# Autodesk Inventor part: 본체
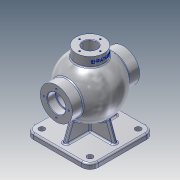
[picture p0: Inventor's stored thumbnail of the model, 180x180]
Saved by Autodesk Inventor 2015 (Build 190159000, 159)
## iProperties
Created: 2025-08
Part Number: 본체
Material: 알루미늄 6061
Document SubType Name: Modeling
Designer: USER
Density: 2.7 g/cm^3
Appearance: 알루미늄 - 평지
Author: USER
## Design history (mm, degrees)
sketch "스케치1"
  geometry: L1 (-62.5, 62.5)-(62.5, 62.5); L2 (62.5, 62.5)-(62.5, -62.5); L3 (62.5, -62.5)-(-62.5, -62.5); L4 (-62.5, -62.5)-(-62.5, 62.5); L5 (-62.5, 62.5)-(62.5, -62.5); L6 (62.5, 62.5)-(-62.5, -62.5); 1 further point
  constraints: 12 end point, 2 midpoint, 2 parallel, 1 horizontal, 1 perpendicular
  dimensions: "d0" = 125 distance of L1.start L1.end; "d1" = 125 distance of L1.end L2.end
extrude "돌출1" new body sketch "스케치1" distance "d2" = 10; taper "d3" = 0 deg
sketch "스케치2"
  geometry: L1 (-62.5, 0)-(62.5, 0) reference; L2 (0, 31)-(0, 139); A1 r 54 centre (0, 85) between (0, 31) and (0, 139); A2 r 44 centre (0, 85) between (0, 41) and (0, 129); 4 further points
  constraints: 4 point on circle, 3 midpoint, 2 centre point, 2 end point, 2 point on line, 2 vertical alignment, 1 coincident, 1 vertical
  dimensions: "d4" = 85 distance from line of L1 A1.centre; "d5" = 54 radius of A1; "d7" = 44 radius of A2
revolve "회전2" sketch "스케치2" stored, may be unused: angle "d8" = 90 deg
node "작업 평면1"
sketch "스케치3"
  geometry: C1 r 27 at (0, 0); 1 further point
  constraints: 1 centre point, 1 coincident
  dimensions: "d10" = 54 diameter of C1
extrude "돌출2" join sketch "스케치3" stored distance "d11" = 10; taper "d12" = 0 deg
hole "구멍1" diameter "d15" = 26; stored, may be unused: countersink angle "d19" = 90 deg, drill point angle "d21" = 0 deg; dims "d16" = 6, "d17" = 4, "d18" = 2, "d20" = 30, "d22" = 10, "d23" = 10
sketch "스케치4"
  geometry: L1 (0, 0)-(0, 20)
  constraints: 2 end point, 1 vertical
  dimensions: "d24" = 20 distance of L1.start L1.end
hole "구멍2" sketch "스케치4" at (0, 20) diameter "d25" = 3.242; stored, may be unused: countersink angle "d29" = 90 deg, drill point angle "d31" = 118 deg; dims "d26" = 9, "d27" = 4, "d28" = 2, "d30" = 11
node "작업 평면2"
sketch "스케치5"
  geometry: L1 (-62.5, 0)-(62.5, 0) reference; C1 r 31 at (0, 85); 2 further points
  constraints: 1 centre point, 1 midpoint, 1 vertical alignment
  dimensions: "d36" = 62 diameter of C1; "d37" = 85 distance from line of C1.centre L1
extrude "돌출3" join sketch "스케치5" stored distance "d38" = 10; taper "d39" = 0 deg
hole "구멍3" diameter "d42" = 30; stored, may be unused: countersink angle "d46" = 90 deg, drill point angle "d48" = 118 deg; dims "d40" = 10, "d41" = 10, "d43" = 9, "d44" = 35, "d45" = 16, "d47" = 40
sketch "스케치6"
  geometry: L1 (0, 0)-(0, 24); C1 r 31 at (0, 0) reference; 1 further point
  constraints: 2 end point, 1 vertical
  dimensions: "d49" = 24 distance of L1.start L1.end
hole "구멍4" sketch "스케치6" at (0, 24) diameter "d50" = 3.242; stored, may be unused: countersink angle "d54" = 90 deg, drill point angle "d56" = 118 deg; dims "d51" = 12, "d52" = 35, "d53" = 16, "d55" = 15
chamfer "모따기1" distance "d61" = 1; stored, may be unused: second distance "d62" = 2, angle "d63" = 45 deg
fillet "모깎기1" dims "d60" = 0.6
chamfer "모따기2" distance "d64" = 1; stored, may be unused: second distance "d65" = 2, angle "d66" = 45 deg
sketch "스케치7"
  geometry: L1 (-62.5, 62.5)-(62.5, 62.5) reference; L2 (62.5, 62.5)-(62.5, -62.5) reference; L3 (62.5, -62.5)-(-62.5, -62.5) reference; L4 (-62.5, -62.5)-(-62.5, 62.5) reference; L5 (50.5, -4)-(-50.5, -4); L6 (-50.5, -4)-(-50.5, 4); L7 (-50.5, 4)-(50.5, 4); L8 (50.5, 4)-(50.5, -4); L9 (50.5, -4)-(-50.5, 4); L10 (-50.5, -4)-(50.5, 4); L11 (4, 50.5)-(-4, 50.5); L12 (-4, 50.5)-(-4, -50.5); L13 (-4, -50.5)-(4, -50.5); L14 (4, -50.5)-(4, 50.5); L15 (4, 50.5)-(-4, -50.5); L16 (-4, 50.5)-(4, -50.5); 1 further point
  constraints: 24 end point, 4 midpoint, 4 parallel, 2 horizontal, 2 perpendicular
  dimensions: "d67" = 8 distance of L5.end L6.end; "d68" = 8 distance of L11.start L11.end; "d69" = 12 distance between parallel lines of L1 L11; "d70" = 12 distance between parallel lines of L4 L6
extrude "돌출4" join sketch "스케치7" stored distance "d71" = 60; taper "d72" = 0 deg
feature "면 기울기1" dims angle "d73" = 20 deg
fillet "모깎기2" dims "d74" = 16
sketch "스케치8"
  geometry: L1 (4, 50.5)-(4, 4) reference; L2 (4, 4)-(50.5, 4) reference; L3 (50.5, 4)-(50.5, -4) reference; L4 (50.5, -4)-(4, -4) reference; L5 (4, -4)-(4, -50.5) reference; L6 (4, -50.5)-(-4, -50.5) reference; L7 (-4, -50.5)-(-4, -4) reference; L8 (-4, -4)-(-50.5, -4) reference; L9 (-50.5, -4)-(-50.5, 4) reference; L10 (-50.5, 4)-(-4, 4) reference; L11 (-4, 4)-(-4, 50.5) reference; L12 (-4, 50.5)-(4, 50.5) reference; L13 (62.5, -46.5)-(62.5, 46.5) reference; L14 (46.5, 62.5)-(-46.5, 62.5) reference; L15 (-62.5, 46.5)-(-62.5, -46.5) reference; L16 (-46.5, -62.5)-(46.5, -62.5) reference; C1 r 5.5 at (46.5, 46.5); C2 r 5.5 at (46.5, -46.5); C3 r 5.5 at (-46.5, -46.5); C4 r 5.5 at (-46.5, 46.5); A1 r 16 centre (46.5, -46.5) between (46.5, -62.5) and (62.5, -46.5) reference; A2 r 16 centre (46.5, 46.5) between (62.5, 46.5) and (46.5, 62.5) reference; A3 r 16 centre (-46.5, 46.5) between (-46.5, 62.5) and (-62.5, 46.5) reference; A4 r 16 centre (-46.5, -46.5) between (-62.5, -46.5) and (-46.5, -62.5) reference; 1 further point
  constraints: 4 centre point, 4 coincident, 3 equal radius
  dimensions: "d75" = 11 diameter of C1
extrude "돌출5" cut sketch "스케치8" stored distance "d76" = 60; taper "d77" = 0 deg
fillet "모깎기3" dims "d78" = 3
fillet "모깎기4" dims "d79" = 3
fillet "모깎기5" dims "d80" = 3
sketch "스케치9"
  geometry: L1 (27, 150)-(-27, 150) reference; 2 further points
  constraints: 1 vertical alignment, 1 other
  dimensions: "d81" = 9 distance from line of point (0, 141) L1
feature "엠보싱1" sketch "스케치9" dims "d0" = 125, "d1" = 125, "d10" = 54, "d82" = 0.5, "d83" = 0
node "솔리드1"
pattern_circular "원형 패턴1" dims angle "d33" = 360 deg
mirror "대칭1"
pattern_circular "원형 패턴3" dims angle "d85" = 360 deg
mirror "대칭2"
node "투영된 루프1"
node "투영된 루프2"
other parameters: "d35" = -65
